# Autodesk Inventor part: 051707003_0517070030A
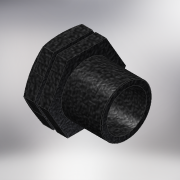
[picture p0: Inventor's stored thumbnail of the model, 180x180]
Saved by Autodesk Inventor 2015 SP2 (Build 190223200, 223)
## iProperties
Created: 2017-05
Part Number: 051707003_0517070030A
Material: Generic
Description: PLASSON PLUG 3/8"
Document SubType Name: Modeling
Designer: Кирилл
Density: 1 g/cm^3
Appearance: Black Cast
Author: Кирилл
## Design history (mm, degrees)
derived "051707.ipt"
feature "Solid1::051707.ipt"
tag "TaggingFeature1"
body "Solid1"
other parameters: "d1" = 16.662, "d2" = 22, "d3" = 13, "d5" = 13, "d6" = 3.42857, "d8" = 0.24, "d12" = 0, "d14" = 1.14286, "d15" = 24, "d16" = 1.37143, "d17" = 3.42857, "d19" = 0, "d21" = 1.98, "d29" = 0, "H_" = 24, "R_" = 16.662, "E_" = 22, "l_2" = 13, "d20" = 3
